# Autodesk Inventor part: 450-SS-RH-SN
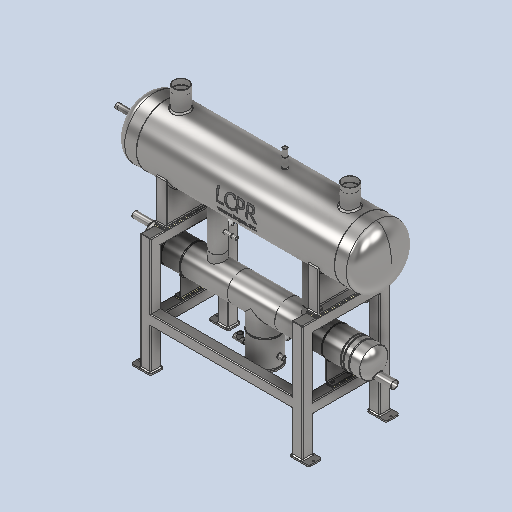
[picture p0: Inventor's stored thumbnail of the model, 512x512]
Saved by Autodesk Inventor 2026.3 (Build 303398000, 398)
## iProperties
Created: 2026-05
Part Number: 450-SS-RH-SN
Material: Generic
Document SubType Name: Modeling
Designer: rva
Density: 1 g/cm^3
Appearance: Default
Author: rva
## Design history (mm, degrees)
derived "LCPR-SS-450-1500-100-SC-200-100-1370-48-50-40-RH-SP-WELDED.i"
body "Solid1"
node "Nylon Heat Tranfer Spacer 175x50.ipt:1"
node "Nylon Heat Tranfer Spacer 175x50.ipt:2"
node "Nylon Heat Tranfer Spacer 460x75.ipt:1"
node "Nylon Heat Tranfer Spacer 460x75.ipt:2"
node "Sub-SS-200-100-1370-48-10-50-40-RH-WELD.iam:1::LCPR-200 SS B"
node "Sub-SS-200-100-1370-48-10-50-40-RH-WELD.iam:1::DIN 2462 Tube"
node "Sub-SS-200-100-1370-48-10-50-40-RH-WELD.iam:1::DIN 2462 Tube"
node "Sub-SS-200-100-1370-48-10-50-40-RH-WELD.iam:1::DIN 2462 Tube"
node "Sub-SS-200-100-1370-48-10-50-40-RH-WELD.iam:1::DIN 2462 Tube"
node "Sub-SS-200-100-1370-48-10-50-40-RH-WELD.iam:1::DIN 2462 Tube"
node "Sub-SS-200-100-1370-48-10-50-40-RH-WELD.iam:1::DIN 2462 Tube"
node "Sub-SS-200-100-1370-48-10-50-40-RH-WELD.iam:1::SS-200 mm Sub"
node "Sub-SS-200-100-1370-48-10-50-40-RH-WELD.iam:1::SS-200 mm Sub"
node "Sub-SS-200-100-1370-48-10-50-40-RH-WELD.iam:1::DIN 2462 Tube"
node "Sub-SS-200-100-1370-48-10-50-40-RH-WELD.iam:1::DIN 2462 Tube"
node "Sub-SS-200-100-1370-48-10-50-40-RH-WELD.iam:1::DIN 2462 Tube"
node "Sub-SS-200-100-1370-48-10-50-40-RH-WELD.iam:1::DIN 2462 Tube"
node "Sub-SS-200-100-1370-48-10-50-40-RH-WELD.iam:1::H1100-R.ipt:1"
node "Sub-SS-200-100-1370-48-10-50-40-RH-WELD.iam:1::H1100-R.ipt:2"
node "Sub-SS-200-100-1370-48-10-50-40-RH-WELD.iam:1::1-2 Inch NPT "
node "Sub-SS-200-100-1370-48-10-50-40-RH-WELD.iam:1::3-4 Inch NPT "
node "Sub-SS-200-100-1370-48-10-50-40-RH-WELD.iam:1::1-2 Inch NPT "
node "Sub-SS-200-100-1370-48-10-50-40-RH-WELD.iam:1::Welds"
node "LCPR-SS-450-1500-100-SP-WELD.iam:1::H1100-R.ipt:1"
node "LCPR-SS-450-1500-100-SP-WELD.iam:1::450 mm SS Dome Cap.ipt:1"
node "LCPR-SS-450-1500-100-SP-WELD.iam:1::450 mm SS Dome Cap.ipt:2"
node "LCPR-SS-450-1500-100-SP-WELD.iam:1::Welds"
node "AS 1112 (2) - Metric M16  Type 10:1"
node "AS 1237 (4.1) 16 mm:1"
node "AS 1237 (4.1) 16 mm:2"
node "AS 1112 (2) - Metric M16  Type 10:2"
node "AS 1237 (4.1) 16 mm:3"
node "AS 1237 (4.1) 16 mm:4"
node "AS 1252 - Metric M16 x 120:2"
node "AS 1112 (2) - Metric M16  Type 10:3"
node "AS 1237 (4.1) 16 mm:5"
node "AS 1237 (4.1) 16 mm:6"
node "AS 1252 - Metric M16 x 120:3"
node "AS 1112 (2) - Metric M16  Type 10:4"
node "AS 1237 (4.1) 16 mm:7"
node "AS 1237 (4.1) 16 mm:8"
node "AS 1252 - Metric M16 x 120:4"
node "AS 1112 (2) - Metric M10  Type 10:1"
node "AS 1237 (D1) 10 mm:1"
node "AS 1237 (D1) 10 mm:2"
node "AS 1111 - Metric M10 x 120:1"
node "AS 1112 (2) - Metric M10  Type 10:2"
node "AS 1237 (D1) 10 mm:3"
node "AS 1237 (D1) 10 mm:4"
node "AS 1111 - Metric M10 x 120:2"
node "AS 1112 (2) - Metric M10  Type 10:3"
node "AS 1237 (D1) 10 mm:5"
node "AS 1237 (D1) 10 mm:6"
node "AS 1111 - Metric M10 x 120:3"
node "AS 1112 (2) - Metric M10  Type 10:4"
node "AS 1237 (D1) 10 mm:7"
node "AS 1237 (D1) 10 mm:8"
node "AS 1111 - Metric M10 x 120:4"
node "Welds"
node "AS 1252 - Metric M16 x 120:5"
node "LCPR-SS-450-1500-100-SC-200-100-1370-48-50-40-RH-SP-WELDED.i"
